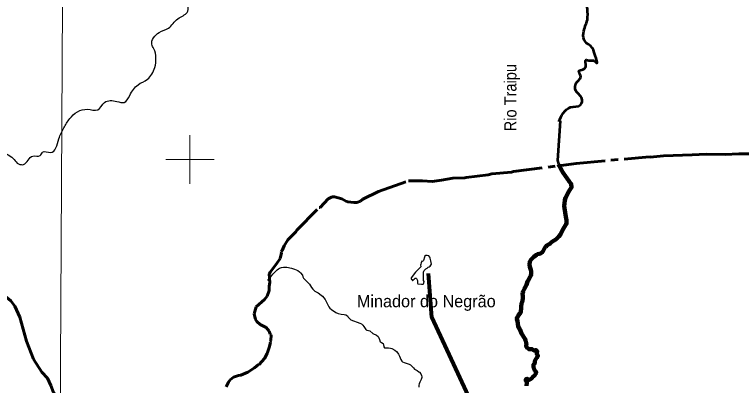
# Model space of a CAD drawing. Extents: x 553962 to 842807, y 8883888 to 9032388.
# Drawn here: x 717768 to 747736, y 8965692 to 8980977 of the extents above; entities that cross this region are included whole.
import ezdxf
from ezdxf.enums import TextEntityAlignment as Align

# ---------------------------------------------------------------- set-up
doc = ezdxf.new("R2010")
doc.units = 0
doc.header["$LTSCALE"] = 200
doc.linetypes.add('LONG_DASH_SHORT_DASH', pattern=[9.9, 6, -1.2, 1.5, -1.2])
for name, color, linetype, lineweight in [('1', 7, 'Continuous', 13), ('2', 7, 'Continuous', 13), ('21', 7, 'Continuous', 25), ('24', 7, 'Continuous', 25), ('28', 7, 'Continuous', 40), ('41', 7, 'Continuous', 40), ('7', 7, 'LONG_DASH_SHORT_DASH', 60), ('9', 7, 'Continuous', 90)]:
    doc.layers.add(name, color=color, linetype=linetype, lineweight=lineweight)
doc.layers.add('49', color=7, linetype='Continuous')

msp = doc.modelspace()

# ---------------------------------------------------------------- linework, layer by layer
at = {"layer": '1'}
msp.add_lwpolyline([(719978.9, 9023574.5), (719561.6, 8949232.2), (719215.6, 8890710.6)], dxfattribs=at)
at = {"layer": '2'}
for p, q in [((725000, 8974000), (725000, 8976000)), ((724000, 8975000), (726000, 8975000))]:
    msp.add_line(p, q, dxfattribs=at)
at = {"layer": '21'}
for points in [[(734441.2, 8970498.9), (734303.8, 8970355.7), (734116.5, 8970129.9), (734113.1, 8970114.7), (734119.4, 8970075.5), (734145.2, 8970051.2), (734168.9, 8970019.5), (734181.4, 8970021.5), (734206.5, 8970050.8), (734247.2, 8970065.8), (734290.4, 8970107.4), (734303.5, 8970111.7), (734321.8, 8970111.1), (734333.6, 8970097.9), (734375, 8970020.5), (734381.7, 8969909.7), (734389.7, 8969884.2), (734396.2, 8969874.8), (734551.2, 8969860.5), (734613.7, 8969866.7), (734627.4, 8969872.6), (734648.3, 8969912.4), (734649.6, 8969980.8), (734634.3, 8970019.7), (734630.8, 8970039.7), (734623.8, 8970209), (734629.4, 8970357.2), (734643.8, 8970405.7), (734658.9, 8970427.2), (734730.6, 8970496.3), (734782.1, 8970530.8), (734817.5, 8970561.3), (734855.2, 8970579.8), (734904.2, 8970611.7), (734951.1, 8970691.3), (734935.8, 8970827.7), (734908.4, 8970936.3), (734891.3, 8970974.5), (734841.3, 8971037.1), (734782.7, 8971051.2)], [(734782.7, 8971051.2), (734756.2, 8971050.8), (734720.8, 8971040.1), (734672, 8971001.4), (734663.3, 8970981.6), (734624.9, 8970837.4), (734592.1, 8970806.3), (734562.4, 8970812), (734543.6, 8970783.7), (734532, 8970740.5), (734512.6, 8970689.2), (734508.8, 8970650.1), (734519.5, 8970599.8), (734514.8, 8970584.3), (734441.2, 8970498.9)]]:
    msp.add_lwpolyline(points, dxfattribs=at)
at = {"layer": '24', "lineweight": 53}
for points in [[(740256.1, 8976602), (740150, 8974957.6), (740199.7, 8974820.8)], [(740199.7, 8974820.8), (740238.1, 8974727.3), (740279.6, 8974643.7), (740334, 8974546.8), (740357.2, 8974493.5), (740382.9, 8974446.8), (740484.1, 8974309.5), (740613.7, 8974119.1), (740717.4, 8973990.4), (740732.3, 8973856.4), (740732.3, 8973856.4), (740732.3, 8973856.4), (740732.3, 8973856.4), (740618, 8973688.2), (740487, 8973417.6), (740453.4, 8973331.1), (740434.4, 8973194.5), (740433.5, 8973090.3), (740439.6, 8973000.5), (740466.4, 8972816.9), (740475.8, 8972719.9), (740503, 8972572.4), (740529.6, 8972497.6), (740528.8, 8972385.3), (740511.7, 8972342.2), (740484.3, 8972292.1), (740351.8, 8972095.1), (740271.5, 8971918), (740212.1, 8971832.2), (740155.8, 8971771.6), (740084.9, 8971712.7), (739981.4, 8971647.3), (739910.7, 8971596.4), (739837.5, 8971524.6), (739757.3, 8971490.6), (739708.7, 8971453.2), (739664.3, 8971410.8), (739632.6, 8971371.3), (739561.2, 8971230.5), (739523.3, 8971179.7), (739487, 8971150), (739449.3, 8971129.7), (739395.4, 8971112.6), (739333.7, 8971101.4), (739290.2, 8971081), (739173.2, 8970993.1), (739094.9, 8970916.4), (739054.2, 8970867.5), (739009.7, 8970790), (739003.8, 8970676.8), (739015.8, 8970579.9), (739051.5, 8970450.1), (739063.7, 8970387.4), (739071.4, 8970367.8), (739072.7, 8970313.5), (739066, 8970263.1), (739051.2, 8970216.4), (739028.1, 8970169.5), (738938.6, 8970019), (738921.2, 8969978.8), (738878.8, 8969842.3), (738791.5, 8969691.8), (738791.5, 8969691.8), (738733.8, 8969568.4), (738716.4, 8969521.7)], [(738716.4, 8969521.7), (738712.1, 8969454.1), (738717.3, 8969381.7), (738726.3, 8969324), (738727.4, 8969273.7), (738715.5, 8969198), (738691.5, 8969119), (738673.7, 8969086.8), (738662.6, 8969043.4), (738652.4, 8968953.5), (738651, 8968849.4), (738637.2, 8968762.8), (738633.9, 8968702.3), (738619.6, 8968671), (738536.5, 8968568.4), (738527.1, 8968550.9), (738521.9, 8968529), (738494.8, 8968495.2), (738481.7, 8968447.9), (738480.1, 8968427.4), (738500, 8968342), (738533.5, 8968133), (738555.2, 8968065.6), (738596.3, 8968005.9), (738628.6, 8967942.3), (738661.9, 8967831), (738818, 8967592.6), (738830.4, 8967556.3)], [(738830.4, 8967556.3), (738834.2, 8967542.6), (738837.7, 8967529), (738840.7, 8967516.2), (738845.7, 8967504.7), (738849.9, 8967492.5), (738850.3, 8967483.6), (738854.3, 8967471.6), (738857.7, 8967458), (738859.7, 8967445.1), (738862.7, 8967432.6), (738865.9, 8967420), (738868.8, 8967405.2), (738868.9, 8967391.8), (738868.2, 8967379), (738865.1, 8967366.3), (738862, 8967353.6), (738859.3, 8967339.4), (738859.3, 8967326.5), (738859.7, 8967313.1), (738863.5, 8967298.8), (738867.7, 8967286), (738870.9, 8967270.3), (738877.9, 8967259.2), (738887.8, 8967249.3), (738899.7, 8967242.8), (738913.1, 8967239.5), (738924.4, 8967232.4), (738934.7, 8967222.3), (738944.1, 8967212.4), (738954.2, 8967202), (738965.1, 8967192.5), (738977.1, 8967186.1), (738992.3, 8967182), (739005.7, 8967183.8), (739018.2, 8967186.9), (739031.3, 8967189.7), (739044.9, 8967190.6), (739058.1, 8967190.6), (739071.4, 8967190.6), (739084.6, 8967190), (739098.8, 8967187.9), (739114.9, 8967178.8), (739126, 8967171), (739135.5, 8967162.6), (739146.5, 8967154.6), (739156.7, 8967146), (739168.6, 8967140), (739183.1, 8967137.6), (739195.8, 8967137.5), (739209, 8967138.7), (739223, 8967141.7), (739237, 8967146.4), (739250.3, 8967150.8), (739263.6, 8967149.5), (739275.9, 8967143.1), (739287.3, 8967135.2), (739296.8, 8967126.4), (739304.9, 8967116.7), (739309.3, 8967110.9)], [(739309.3, 8967110.9), (739317.7, 8967092.1), (739317.8, 8967077.7), (739313.7, 8967065.7), (739305.1, 8967055.2), (739299.2, 8967042.7), (739293.7, 8967028), (739293.7, 8967013.7), (739293.7, 8966998.3), (739298.7, 8966985.1), (739306.6, 8966974), (739315.2, 8966964.3), (739323.7, 8966955), (739332.4, 8966945.1), (739340.5, 8966934.7), (739344.5, 8966922.3), (739344.1, 8966907.1), (739339.7, 8966894.5), (739332.7, 8966881.9), (739327, 8966869.6), (739321, 8966858), (739310, 8966847.7), (739297.7, 8966839.9), (739289.1, 8966830.7), (739280.9, 8966819.4), (739274.4, 8966807.4), (739268.6, 8966795.2), (739262.3, 8966783.3), (739255.3, 8966770.6), (739248.4, 8966758.7), (739242.6, 8966746.5), (739234.9, 8966729.8), (739229.9, 8966717.1), (739226, 8966704.3), (739221.5, 8966691.2), (739217.6, 8966678.8), (739216.4, 8966666), (739216.6, 8966653.4), (739217.7, 8966639.2), (739219.6, 8966626.8), (739217.9, 8966613.5), (739211.8, 8966601.6), (739204.7, 8966591), (739196.1, 8966581.6), (739184.1, 8966571.9), (739172.9, 8966564.1), (739164.8, 8966554.4), (739158.5, 8966543), (739158.1, 8966530), (739159.4, 8966517.4), (739159.7, 8966501.9), (739159.6, 8966488.5), (739159.6, 8966475.8), (739159.8, 8966461.7), (739161.8, 8966447.6), (739165.8, 8966434.4), (739172.5, 8966418), (739176.8, 8966405.2), (739180.7, 8966392.1), (739185.8, 8966379.3), (739190.3, 8966367.7), (739195.8, 8966353.6), (739200.5, 8966339.5), (739206, 8966326.4), (739212.5, 8966314.9)], [(739212.5, 8966314.9), (739221.2, 8966303.3), (739229.4, 8966293.7), (739238.7, 8966284), (739248.2, 8966272.7), (739257.8, 8966260.7), (739267.2, 8966248.6), (739271.9, 8966236.2), (739271.7, 8966223.1), (739269.6, 8966210.1), (739265.5, 8966197.1), (739259.7, 8966183.4), (739251.7, 8966172.8), (739243.5, 8966161.9), (739235.5, 8966149.4), (739228.5, 8966135.9), (739219.9, 8966122.7), (739212.2, 8966112.6), (739203.3, 8966100.1), (739194.2, 8966089), (739184.2, 8966080.5), (739173, 8966072.4), (739161.1, 8966064.8), (739147.8, 8966055.7), (739137.4, 8966046.1), (739127.2, 8966033.7), (739118.7, 8966022.8), (739108.3, 8966010.4), (739099.8, 8966000.7), (739090.7, 8965990.6), (739081.8, 8965981.7), (739068.4, 8965968.8), (739057.5, 8965961.5), (739046.3, 8965954.5), (739034.9, 8965947), (739019.6, 8965939.2), (739005.3, 8965931.5)], [(739005.3, 8965931.5), (738993.5, 8965925.7), (738980.6, 8965921), (738966.6, 8965918), (738953.9, 8965919.7), (738942.8, 8965926.2), (738932.8, 8965935.4), (738924.7, 8965947.7), (738916.9, 8965957.7), (738899.6, 8965959.3), (738885.1, 8965958.9), (738871.5, 8965956.5), (738857.8, 8965952.8), (738845.7, 8965947.2), (738840.1, 8965935.1), (738840, 8965921.4), (738840.2, 8965908), (738843.6, 8965895.1), (738851.5, 8965882.9), (738858, 8965870.6), (738863, 8965858.1), (738868.1, 8965843.9), (738874.6, 8965831.2), (738882.9, 8965819.4), (738888.6, 8965805.6), (738890.4, 8965789.8), (738890.2, 8965775.9), (738888.7, 8965761.5), (738884.4, 8965749.3), (738879.3, 8965737.4), (738877.1, 8965724.5), (738874.1, 8965709.8), (738870.9, 8965696.6), (738868, 8965682.8)]]:
    msp.add_lwpolyline(points, dxfattribs=at)
at = {"layer": '24'}
for points in [[(728214.3, 8970014.3), (728272, 8970092.8), (728331.6, 8970162.7), (728417.4, 8970282.5), (728594.8, 8970457.4), (728648.4, 8970499.8), (728691.9, 8970528.1), (728779.9, 8970559.1)], [(728779.9, 8970559.1), (728852.1, 8970572.7), (728924.3, 8970573), (729000.6, 8970564.2), (729191.8, 8970527), (729315.4, 8970483.8), (729446.4, 8970430), (729519.7, 8970374), (729562.9, 8970331.7), (729643.8, 8970234.4), (729657.8, 8970174.1), (729686.6, 8970110.8), (729928.3, 8969870.5), (730012.4, 8969726.4), (730069.7, 8969653.9), (730149.2, 8969579.5), (730284.8, 8969503.9), (730412, 8969418.7), (730463.2, 8969367.6), (730567.7, 8969229.8), (730688.7, 8969016.5), (730730.3, 8968933.7), (730772.2, 8968877.4), (730829.8, 8968823.3), (731008.2, 8968703.6), (731105.3, 8968654.8), (731233, 8968624.6), (731360.6, 8968619.3), (731432.2, 8968607.5), (731490.4, 8968564.6), (731529, 8968498.9), (731572, 8968444.1), (731629.2, 8968401.6), (732006.1, 8968259.5), (732068.7, 8968231.4), (732130.1, 8968177.5), (732172.3, 8968124.3), (732254.1, 8968003.8), (732270.8, 8967986), (732292.3, 8967973.5), (732359.4, 8967962.3), (732419.1, 8967940.3), (732541.4, 8967832.4), (732686.6, 8967768.5), (732762.4, 8967705.5), (732787.2, 8967659.9), (732807.8, 8967584.8), (732842.4, 8967493.1), (732851.1, 8967484), (732892.3, 8967462.8), (732967.3, 8967414.9), (732986, 8967300), (732997.8, 8967278.1), (733022.8, 8967248.5), (733047.5, 8967241.4), (733120.3, 8967238.6), (733188.8, 8967243.5), (733264.7, 8967233.7), (733328, 8967214.7), (733447.7, 8967146.1), (733512.9, 8967086.8), (733564.5, 8967027.4), (733599.2, 8966975.3), (733599.2, 8966975.3), (733635.8, 8966903.5)], [(733635.8, 8966903.5), (733667.4, 8966823.6), (733697.2, 8966763.3), (733739, 8966694.9), (733760.7, 8966668.4), (733825.8, 8966637.8), (733959, 8966591.6), (734034.5, 8966569.7), (734094.6, 8966536.2), (734151.5, 8966485), (734209.2, 8966415.7), (734259.6, 8966363.7), (734370.9, 8966301.9), (734433.4, 8966256), (734458.6, 8966232.5), (734511.2, 8966171.1), (734552, 8966096.3), (734560.3, 8966041.1), (734559.6, 8966020.2), (734537.3, 8965930.7), (734471.1, 8965828), (734446.2, 8965764.4), (734439.5, 8965701), (734438, 8965620.3)]]:
    msp.add_lwpolyline(points, dxfattribs=at)
msp.add_spline([(715037, 8973071.8), (715705.1, 8973746.2), (715968.5, 8974273.5), (716313.1, 8974881.9), (716799.5, 8975226.6), (717083.2, 8975429.4), (717285.9, 8975328), (717752, 8975003.5), (717934.4, 8974821), (718137.1, 8974800.7), (718522.2, 8975145.5), (718826.2, 8975165.8), (718927.5, 8975307.7), (719251.8, 8975287.5), (719596.3, 8975855.3), (719799, 8976301.5), (720042.2, 8976686.8), (720771.8, 8977072.1), (721197.4, 8977051.8), (721481.2, 8977356), (721987.8, 8977396.6), (722291.8, 8977356), (722514.8, 8977639.9), (722859.3, 8978086.1), (723244.4, 8978309.2), (723548.4, 8978795.9), (723507.9, 8979566.5), (723426.8, 8979749.1), (723730.8, 8980235.8), (724115.9, 8980418.3), (724501, 8980803.6), (724886, 8981067.2), (724886, 8981594.5), (724865.8, 8981939.3), (725068.4, 8982385.5), (725169.8, 8982831.6), (725331.9, 8983216.9), (725311.6, 8983582), (725473.8, 8983825.3), (725696.7, 8983987.6), (725777.8, 8984433.7), (725858.8, 8984636.5), (726183.1, 8984636.5), (726162.8, 8984920.5), (726284.5, 8985163.8), (726588.5, 8985569.4), (726993.8, 8986056.1), (726770.9, 8986299.5), (726466.9, 8986238.7), (726264.2, 8986340.1), (726527.7, 8986563.1), (726487.1, 8986745.7), (726770.9, 8986907.9), (727155.9, 8987090.4), (727297.8, 8987171.5), (727338.3, 8987496), (727581.6, 8987698.8), (727743.7, 8987921.9), (727905.8, 8988084.1), (728068, 8988408.6), (728351.7, 8988510), (728453, 8988814.2), (728655.7, 8988854.8), (728676, 8989098.1), (728898.9, 8989260.4), (729121.8, 8989260.4), (729284, 8989037.3), (729527.2, 8988733.1), (729750.1, 8988712.8), (729973.1, 8988834.5), (729993.3, 8988753.4), (730054.1, 8988530.3), (730135.2, 8988469.4), (730358.1, 8988469.4), (730459.5, 8988408.6), (730702.7, 8988489.7), (730702.7, 8988611.4), (730885.1, 8988652), (731067.5, 8988469.4), (731168.8, 8988347.8), (731472.8, 8988368), (731736.3, 8988631.7), (731857.9, 8988834.5), (732222.7, 8988814.2), (732324, 8989017), (732506.4, 8989138.7), (732547, 8989300.9), (732851, 8989402.3), (733073.9, 8989382), (733114.4, 8989666), (733215.8, 8989848.5)], degree=3, dxfattribs=at)
at = {"layer": '24', "lineweight": 53}
msp.add_spline([(740207.8, 8976565.1), (740390.3, 8976909.9), (740694.3, 8977153.2), (741099.6, 8977254.6), (741160.4, 8977518.3), (741038.8, 8977680.5), (740876.7, 8977923.9), (740998.3, 8978248.3), (741099.6, 8978370), (741099.6, 8978471.4), (741038.8, 8978653.9), (741200.9, 8978714.8), (741322.5, 8978836.5), (741322.5, 8979100.1), (741484.7, 8979079.8), (741646.8, 8979079.8), (741768.4, 8978978.4), (741707.6, 8979282.6), (741525.2, 8979667.9), (741302.3, 8979850.5), (741221.2, 8980215.5), (741383.3, 8980763.1), (741383.3, 8981209.2), (741383.3, 8981432.3), (741991.3, 8982770.8), (742356.2, 8983723.9), (742417, 8984271.5), (742741.2, 8985042.1), (742903.4, 8985812.8), (743106, 8986218.4), (743470.8, 8986380.6), (743734.3, 8986887.6), (743734.3, 8987354.1), (744038.3, 8987354.1), (744322.1, 8987658.2), (744342.3, 8987881.3), (744524.7, 8988145), (744686.9, 8988266.7), (744849, 8988408.6), (745031.4, 8988347.8), (745274.6, 8988205.8), (745416.5, 8988205.8), (745598.9, 8988388.3), (745659.7, 8988631.7)], degree=3, dxfattribs=at)
at = {"layer": '28', "lineweight": 80}
msp.add_lwpolyline([(756666.9, 8960280.5), (753769.9, 8960761.1), (752238.8, 8960190.3), (744706.3, 8961816), (738249.1, 8961416.3), (734964.7, 8968490.1), (734839.6, 8970305.5)], dxfattribs=at)
at = {"layer": '7'}
for points in [[(728775.4, 8971157.2), (728762.8, 8971215.3), (728807.7, 8971247.8), (728882.9, 8971442.9), (729041.4, 8971697.8), (729364.5, 8972018.1), (729404.2, 8972096.7), (730321.7, 8973018.8), (730368.4, 8973026), (730699.4, 8973383.6), (730862, 8973459.9), (730956.1, 8973460), (731265.8, 8973385.6), (731447.8, 8973274.4), (731473.6, 8973278.5), (731501.8, 8973259.3), (731752.1, 8973224.9), (731885.4, 8973232.8), (732033.3, 8973290.9), (732132.7, 8973369.8), (732767.6, 8973679.2), (734004.4, 8974123.6), (734587.5, 8974117.1), (734986.3, 8974093.8), (735372.7, 8974147.2), (735835.4, 8974235.1), (736327.4, 8974244.9), (736385.3, 8974265.2), (737292.2, 8974376.7), (737450.9, 8974411), (738250.7, 8974481.5), (738334.6, 8974505.4), (740923.3, 8974839.9), (743944.6, 8975116), (743973.3, 8975101.7), (744524.3, 8975159.5), (745697.7, 8975189)], [(745697.7, 8975189), (745697.7, 8975189), (746278.3, 8975226), (747060.9, 8975214.3), (747626.8, 8975234.9), (748067.1, 8975233)], [(726489.2, 8965641.2), (726585.3, 8965827.1), (726663.7, 8965928.8), (726797, 8966026.6), (727004.8, 8966100.9), (727095.2, 8966112.8), (727389.2, 8966234.1), (727665.8, 8966411.4), (727830.4, 8966559.9), (727853.4, 8966559.4), (728073.8, 8966803.2), (728177.3, 8967005.8), (728281, 8967292.8), (728314.3, 8967479.3), (728306, 8967500.6), (728333.7, 8967541.7), (728350.7, 8967781.6), (728305.9, 8967811.8), (728268.5, 8967931), (728143.1, 8968083.6), (727891.6, 8968208.7), (727752.6, 8968328.3), (727699.6, 8968412.7), (727644.7, 8968647.4), (727727.1, 8968929.1), (728078.2, 8969238.6), (728184.2, 8969376), (728262.5, 8969602.8), (728262.6, 8969767.2), (728287.9, 8969948.7), (728268.9, 8970282.4), (728302.9, 8970356.4), (728566.6, 8970704.3), (728713.2, 8970930.1), (728775.4, 8971157.2)], [(714387.4, 8969902.2), (714562.6, 8969724), (714791.2, 8969580.7), (715019.8, 8969437.3), (715266.3, 8969329.2), (715566.5, 8969291.3), (716240, 8969497.5), (716452.6, 8969548.7), (716647.3, 8969582.3), (716912.5, 8969580.1), (717194.9, 8969524.6), (717616.1, 8969176.7), (717779.5, 8968954.6), (717981.6, 8968510.6), (718255.9, 8967518.7), (718550, 8966774), (718899, 8966240.8), (719126.6, 8965991.5), (719265.4, 8965689.9), (719369.1, 8965406.3), (719491, 8965193.2), (719658.3, 8965140.1)]]:
    msp.add_lwpolyline(points, dxfattribs=at)
at = {"layer": '9'}
for points in [[(740210.1, 8974795.4), (740238.1, 8974727.3), (740279.6, 8974643.7), (740334, 8974546.8), (740357.2, 8974493.5), (740382.9, 8974446.8), (740484.1, 8974309.5), (740613.7, 8974119.1), (740717.4, 8973990.4), (740732.3, 8973856.4), (740732.3, 8973856.4), (740732.3, 8973856.4), (740732.3, 8973856.4), (740618, 8973688.2), (740487, 8973417.6), (740453.4, 8973331.1), (740434.4, 8973194.5), (740433.5, 8973090.3), (740439.6, 8973000.5), (740466.4, 8972816.9), (740475.8, 8972719.9), (740503, 8972572.4), (740529.6, 8972497.6), (740528.8, 8972385.3), (740511.7, 8972342.2), (740484.3, 8972292.1), (740351.8, 8972095.1), (740271.5, 8971918), (740212.1, 8971832.2), (740155.8, 8971771.6), (740084.9, 8971712.7), (739981.4, 8971647.3), (739910.7, 8971596.4), (739837.5, 8971524.6), (739757.3, 8971490.6), (739708.7, 8971453.2), (739664.3, 8971410.8), (739632.6, 8971371.3), (739561.2, 8971230.5), (739523.3, 8971179.7), (739487, 8971150), (739449.3, 8971129.7), (739395.4, 8971112.6), (739333.7, 8971101.4), (739290.2, 8971081), (739173.2, 8970993.1), (739094.9, 8970916.4), (739054.2, 8970867.5), (739009.7, 8970790), (739003.8, 8970676.8), (739015.8, 8970579.9), (739051.5, 8970450.1), (739063.7, 8970387.4), (739071.4, 8970367.8), (739072.7, 8970313.5), (739066, 8970263.1), (739051.2, 8970216.4), (739028.1, 8970169.5), (738938.6, 8970019), (738921.2, 8969978.8), (738878.8, 8969842.3), (738791.5, 8969691.8), (738791.5, 8969691.8), (738733.8, 8969568.4), (738716.4, 8969521.7)], [(738716.4, 8969521.7), (738712.1, 8969454.1), (738717.3, 8969381.7), (738726.3, 8969324), (738727.4, 8969273.7), (738715.5, 8969198), (738691.5, 8969119), (738673.7, 8969086.8), (738662.6, 8969043.4), (738652.4, 8968953.5), (738651, 8968849.4), (738637.2, 8968762.8), (738633.9, 8968702.3), (738619.6, 8968671), (738536.5, 8968568.4), (738527.1, 8968550.9), (738521.9, 8968529), (738494.8, 8968495.2), (738481.7, 8968447.9), (738480.1, 8968427.4), (738500, 8968342), (738533.5, 8968133), (738555.2, 8968065.6), (738596.3, 8968005.9), (738628.6, 8967942.3), (738661.9, 8967831), (738818, 8967592.6), (738830.4, 8967556.3)], [(738830.4, 8967556.3), (738834.2, 8967542.6), (738837.7, 8967529), (738840.7, 8967516.2), (738845.7, 8967504.7), (738849.9, 8967492.5), (738850.3, 8967483.6), (738854.3, 8967471.6), (738857.7, 8967458), (738859.7, 8967445.1), (738862.7, 8967432.6), (738865.9, 8967420), (738868.8, 8967405.2), (738868.9, 8967391.8), (738868.2, 8967379), (738865.1, 8967366.3), (738862, 8967353.6), (738859.3, 8967339.4), (738859.3, 8967326.5), (738859.7, 8967313.1), (738863.5, 8967298.8), (738867.7, 8967286), (738870.9, 8967270.3), (738877.9, 8967259.2), (738887.8, 8967249.3), (738899.7, 8967242.8), (738913.1, 8967239.5), (738924.4, 8967232.4), (738934.7, 8967222.3), (738944.1, 8967212.4), (738954.2, 8967202), (738965.1, 8967192.5), (738977.1, 8967186.1), (738992.3, 8967182), (739005.7, 8967183.8), (739018.2, 8967186.9), (739031.3, 8967189.7), (739044.9, 8967190.6), (739058.1, 8967190.6), (739071.4, 8967190.6), (739084.6, 8967190), (739098.8, 8967187.9), (739114.9, 8967178.8), (739126, 8967171), (739135.5, 8967162.6), (739146.5, 8967154.6), (739156.7, 8967146), (739168.6, 8967140), (739183.1, 8967137.6), (739195.8, 8967137.5), (739209, 8967138.7), (739223, 8967141.7), (739237, 8967146.4), (739250.3, 8967150.8), (739263.6, 8967149.5), (739275.9, 8967143.1), (739287.3, 8967135.2), (739296.8, 8967126.4), (739304.9, 8967116.7), (739309.3, 8967110.9)], [(739309.3, 8967110.9), (739317.7, 8967092.1), (739317.8, 8967077.7), (739313.7, 8967065.7), (739305.1, 8967055.2), (739299.2, 8967042.7), (739293.7, 8967028), (739293.7, 8967013.7), (739293.7, 8966998.3), (739298.7, 8966985.1), (739306.6, 8966974), (739315.2, 8966964.3), (739323.7, 8966955), (739332.4, 8966945.1), (739340.5, 8966934.7), (739344.5, 8966922.3), (739344.1, 8966907.1), (739339.7, 8966894.5), (739332.7, 8966881.9), (739327, 8966869.6), (739321, 8966858), (739310, 8966847.7), (739297.7, 8966839.9), (739289.1, 8966830.7), (739280.9, 8966819.4), (739274.4, 8966807.4), (739268.6, 8966795.2), (739262.3, 8966783.3), (739255.3, 8966770.6), (739248.4, 8966758.7), (739242.6, 8966746.5), (739234.9, 8966729.8), (739229.9, 8966717.1), (739226, 8966704.3), (739221.5, 8966691.2), (739217.6, 8966678.8), (739216.4, 8966666), (739216.6, 8966653.4), (739217.7, 8966639.2), (739219.6, 8966626.8), (739217.9, 8966613.5), (739211.8, 8966601.6), (739204.7, 8966591), (739196.1, 8966581.6), (739184.1, 8966571.9), (739172.9, 8966564.1), (739164.8, 8966554.4), (739158.5, 8966543), (739158.1, 8966530), (739159.4, 8966517.4), (739159.7, 8966501.9), (739159.6, 8966488.5), (739159.6, 8966475.8), (739159.8, 8966461.7), (739161.8, 8966447.6), (739165.8, 8966434.4), (739172.5, 8966418), (739176.8, 8966405.2), (739180.7, 8966392.1), (739185.8, 8966379.3), (739190.3, 8966367.7), (739195.8, 8966353.6), (739200.5, 8966339.5), (739206, 8966326.4), (739212.5, 8966314.9)], [(739212.5, 8966314.9), (739221.2, 8966303.3), (739229.4, 8966293.7), (739238.7, 8966284), (739248.2, 8966272.7), (739257.8, 8966260.7), (739267.2, 8966248.6), (739271.9, 8966236.2), (739271.7, 8966223.1), (739269.6, 8966210.1), (739265.5, 8966197.1), (739259.7, 8966183.4), (739251.7, 8966172.8), (739243.5, 8966161.9), (739235.5, 8966149.4), (739228.5, 8966135.9), (739219.9, 8966122.7), (739212.2, 8966112.6), (739203.3, 8966100.1), (739194.2, 8966089), (739184.2, 8966080.5), (739173, 8966072.4), (739161.1, 8966064.8), (739147.8, 8966055.7), (739137.4, 8966046.1), (739127.2, 8966033.7), (739118.7, 8966022.8), (739108.3, 8966010.4), (739099.8, 8966000.7), (739090.7, 8965990.6), (739081.8, 8965981.7), (739068.4, 8965968.8), (739057.5, 8965961.5), (739046.3, 8965954.5), (739034.9, 8965947), (739019.6, 8965939.2), (739005.3, 8965931.5)], [(739005.3, 8965931.5), (738993.5, 8965925.7), (738980.6, 8965921), (738966.6, 8965918), (738953.9, 8965919.7), (738942.8, 8965926.2), (738932.8, 8965935.4), (738924.7, 8965947.7), (738916.9, 8965957.7), (738899.6, 8965959.3), (738885.1, 8965958.9), (738871.5, 8965956.5), (738857.8, 8965952.8), (738845.7, 8965947.2), (738840.1, 8965935.1), (738840, 8965921.4), (738840.2, 8965908), (738843.6, 8965895.1), (738851.5, 8965882.9), (738858, 8965870.6), (738863, 8965858.1), (738868.1, 8965843.9), (738874.6, 8965831.2), (738882.9, 8965819.4), (738888.6, 8965805.6), (738890.4, 8965789.8), (738890.2, 8965775.9), (738888.7, 8965761.5), (738884.4, 8965749.3), (738879.3, 8965737.4), (738877.1, 8965724.5), (738874.1, 8965709.8), (738870.9, 8965696.6), (738868, 8965682.8)]]:
    msp.add_lwpolyline(points, dxfattribs=at)

# ---------------------------------------------------------------- texts
at = {"layer": '41'}
msp.add_text('Minador do Negrão', height=500, dxfattribs=at).set_placement((731880.7, 8968914.6))
at = {"layer": '49', "width": 0.9}
msp.add_text('Rio Traipu', height=500, rotation=90, dxfattribs=at).set_placement((738459.1, 8977551.3), align=Align.CENTER)

doc.saveas('drawing.dxf')
